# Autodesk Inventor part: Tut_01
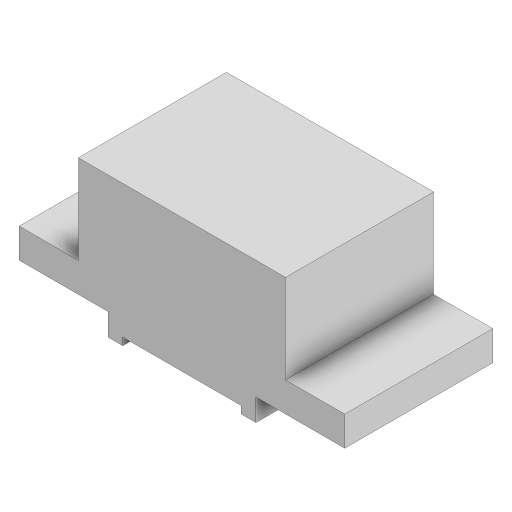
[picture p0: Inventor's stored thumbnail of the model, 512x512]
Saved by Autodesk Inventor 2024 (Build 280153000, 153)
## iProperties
Created: 2022-07
Part Number: Tut_01
Material: Generic
Document SubType Name: Modeling
Designer: LENOVO-CADCIM
Density: 1 g/cm^3
Appearance: Default
Author: LENOVO-CADCIM
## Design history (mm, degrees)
sketch "Sketch1"
  geometry: L1 (0, 0)-(50.8, 0); L2 (50.8, 0)-(50.8, -6.35); L3 (50.8, -6.35)-(63.5, -6.35); L4 (63.5, -6.35)-(63.5, 12.7); L5 (63.5, 12.7)-(139.7, 12.7); L6 (139.7, 12.7)-(139.7, 38.1); L7 (139.7, 38.1)-(88.9, 38.1); L8 (88.9, 38.1)-(88.9, 114.3); L9 (88.9, 114.3)-(-88.9, 114.3); L10 (-88.9, 114.3)-(-88.9, 38.1); L11 (-88.9, 38.1)-(-139.7, 38.1); L12 (-139.7, 38.1)-(-139.7, 12.7); L13 (-139.7, 12.7)-(-63.5, 12.7); L14 (-63.5, 12.7)-(-63.5, -6.35); L15 (-63.5, -6.35)-(-50.8, -6.35); L16 (-50.8, -6.35)-(-50.8, 0); L17 (-50.8, 0)-(0, 0)
  constraints: 34 end point, 12 perpendicular, 2 point on line, 1 horizontal, 1 vertical
  dimensions: "d0" = 50.8 distance of L1.start L1.end; "d1" = 6.35 distance of L1.end L2.end; "d2" = 12.7 distance of L2.end L3.end; "d3" = 19.05 distance of L3.end L4.end; "d4" = 76.2 distance of L4.end L5.end; "d5" = 25.4 distance of L5.end L6.end; "d6" = 50.8 distance of L6.end L7.end; "d7" = 76.2 distance of L7.end L8.end; "d8" = 177.8 distance of L8.end L9.end; "d9" = 76.2 distance of L9.end L10.end; "d10" = 50.8 distance of L10.end L11.end; "d12" = 25.4 distance of L11.end L12.end; "d13" = 76.2 distance of L12.end L13.end; "d14" = 19.05 distance of L13.end L14.end; "d15" = 12.7 distance of L14.end L15.end; "d16" = 6.35 distance of L15.end L16.end; "d17" = 50.8 distance of L16.end L1.start (derived)
extrude "Extrusion1" new body sketch "Sketch1" distance "d18" = 127; taper "d19" = 0 deg
body "Solid1"
